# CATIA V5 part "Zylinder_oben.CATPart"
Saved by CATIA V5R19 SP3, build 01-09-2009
Part number: Zylinder_oben
Bounding box of the stored display mesh (mm): x -15 to 15, y -15 to 15, z -15 to 160
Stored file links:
  C:\Users\Timo\Desktop\Hexapod\Zylinder_oben.CATPart
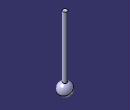
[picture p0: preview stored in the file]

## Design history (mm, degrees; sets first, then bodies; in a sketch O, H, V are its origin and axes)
Set1
  Plane1: type Offset, RefPlane xy-plane, Offset 10
Body1 (main body)
  Sketch1 on xy-plane, origin (0, 0, 0), H (0, 1, 0), V (-1, 0, 0)
    axis line L1 (-130.0335, 0) -> (145.1636, 0)
    point P1 (-130.0335, 0)
    arc A1 centre (0, 0) radius 15 from (15, 0) to (-15, 0) ccw
    point P3 (-15, 0)
    point P4 (15, 0)
    radius A1 = 15
    coincidence: P1 H, P3 L1, P4 L1
    horizontal: L1 H
  Shaft1: profile Sketch1, axis Sketch1.L1, angle 360
  Sketch2 on Plane1, origin (0, 0, 10), H (0, 1, 0), V (-1, 0, 0)
    circle A1 centre (0, 0) radius 5
    radius A1 = 5
  Pad1: profile Sketch2, direction (0, 0, 1), length 150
